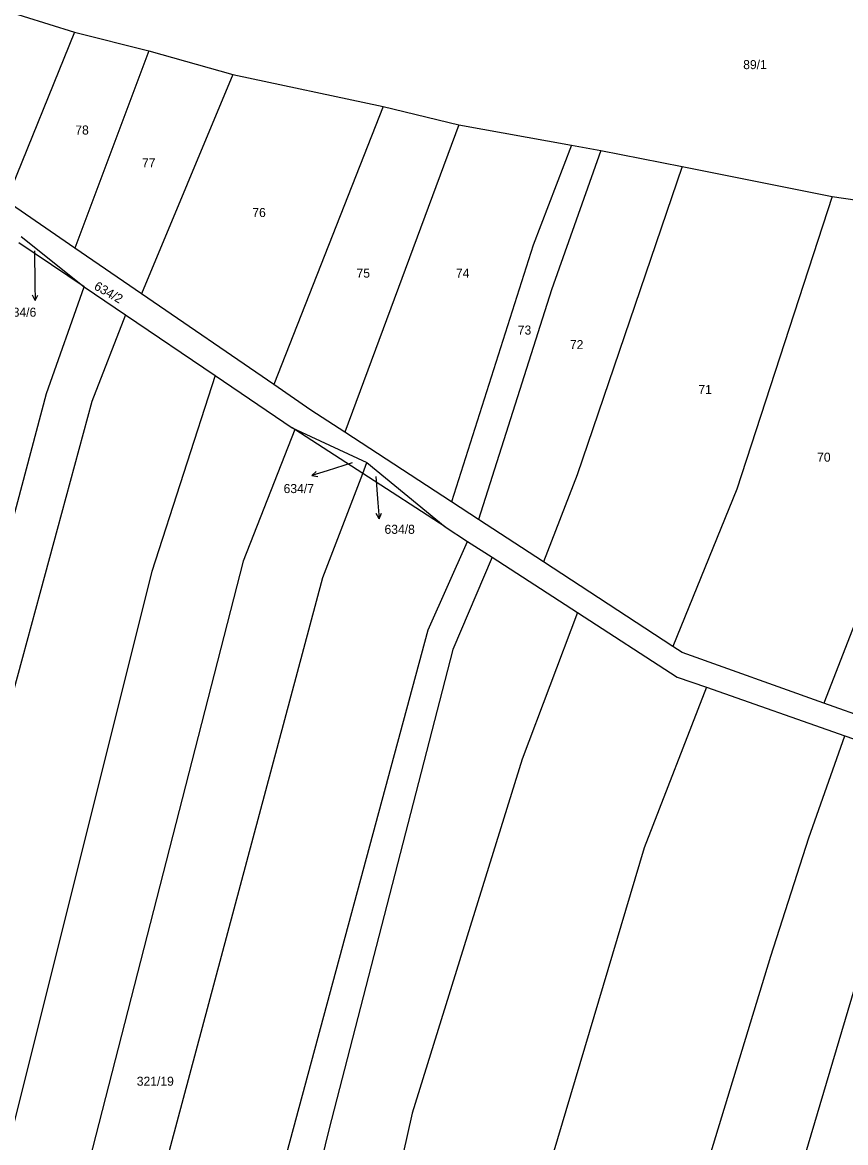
# Model space of a CAD drawing. Extents: x -746176 to -739709, y -1128407 to -1124482.
# Drawn here: x -743602.7 to -743448.2, y -1127556.1 to -1127345.9 of the extents above; entities that cross this region are included whole.
import ezdxf

# ---------------------------------------------------------------- set-up
doc = ezdxf.new("R2010")
doc.units = 0
for name, color, linetype in [('Hranice parcel', 7, 'Continuous'), ('Parcelní čísla', 7, 'Continuous'), ('Pop  PČ popisy', 7, 'Continuous')]:
    doc.layers.add(name, color=color, linetype=linetype)

msp = doc.modelspace()

# ---------------------------------------------------------------- linework, layer by layer
at = {"layer": 'Hranice parcel'}
for p, q in [((-743608.18, -1127342.94), (-743592.88, -1127347.72)), ((-743592.88, -1127347.72), (-743605.72, -1127379.4)), ((-743592.88, -1127347.72), (-743578.94, -1127351.24)), ((-743578.94, -1127351.24), (-743592.83, -1127388.25)), ((-743578.94, -1127351.24), (-743563.19, -1127355.67)), ((-743563.19, -1127355.67), (-743580.36, -1127396.81)), ((-743563.19, -1127355.67), (-743534.99, -1127361.65)), ((-743534.99, -1127361.65), (-743555.5, -1127413.88)), ((-743534.99, -1127361.65), (-743520.78, -1127365.13)), ((-743520.78, -1127365.13), (-743542.21, -1127422.8)), ((-743520.78, -1127365.13), (-743499.65, -1127368.91)), ((-743499.65, -1127368.91), (-743494.17, -1127369.95)), ((-743494.17, -1127369.95), (-743478.91, -1127372.96)), ((-743478.91, -1127372.96), (-743450.74, -1127378.54)), ((-743450.74, -1127378.54), (-743421.13, -1127383.11)), ((-743592.83, -1127388.25), (-743605.72, -1127379.4)), ((-743602.9, -1127386.07), (-743591.07, -1127395.53)), ((-743591.07, -1127395.53), (-743603.32, -1127387.24)), ((-743580.36, -1127396.81), (-743592.83, -1127388.25)), ((-743591.07, -1127395.53), (-743583.33, -1127400.78)), ((-743555.5, -1127413.88), (-743580.36, -1127396.81)), ((-743583.33, -1127400.78), (-743566.53, -1127412.16)), ((-743566.53, -1127412.16), (-743552.04, -1127421.98)), ((-743551.54, -1127422.32), (-743552.04, -1127421.98)), ((-743552.04, -1127421.98), (-743538.08, -1127428.5)), ((-743538.8, -1127430.57), (-743551.54, -1127422.32)), ((-743522.16, -1127435.9), (-743542.21, -1127422.8)), ((-743538.8, -1127430.57), (-743538.08, -1127428.5)), ((-743538.08, -1127428.5), (-743523.36, -1127440.58)), ((-743523.36, -1127440.58), (-743538.8, -1127430.57)), ((-743517.11, -1127439.2), (-743522.16, -1127435.9)), ((-743504.93, -1127447.16), (-743517.11, -1127439.2)), ((-743523.36, -1127440.58), (-743519.14, -1127443.31)), ((-743519.14, -1127443.31), (-743514.57, -1127446.27)), ((-743514.57, -1127446.27), (-743498.56, -1127456.64)), ((-743480.64, -1127463.02), (-743504.93, -1127447.16)), ((-743474.35, -1127470.68), (-743448.36, -1127479.77)), ((-743435.76, -1127479.58), (-743452.29, -1127473.67)), ((-743448.36, -1127479.77), (-743431.85, -1127485.54))]:
    msp.add_line(p, q, dxfattribs=at)
for points in [[(-743499.65, -1127368.91), (-743506.82, -1127387.68), (-743522.16, -1127435.9)], [(-743494.17, -1127369.95), (-743503.41, -1127396.1), (-743517.11, -1127439.2)], [(-743478.91, -1127372.96), (-743498.61, -1127430.83), (-743504.93, -1127447.16)], [(-743450.74, -1127378.54), (-743468.63, -1127433.52), (-743480.64, -1127463.02)], [(-743421.13, -1127383.11), (-743430.01, -1127406.91), (-743443.41, -1127450.8), (-743452.29, -1127473.67)], [(-743681.73, -1127737.55), (-743673.31, -1127708.75), (-743643.68, -1127594.43), (-743625.08, -1127516.64), (-743598.16, -1127415.52), (-743591.07, -1127395.53)], [(-743583.33, -1127400.78), (-743589.64, -1127417.03), (-743612.49, -1127501.11), (-743625.94, -1127556.86), (-743649.9, -1127650.85), (-743673.66, -1127737.68)], [(-743566.53, -1127412.16), (-743578.37, -1127448.95), (-743606.94, -1127562.76), (-743640.25, -1127693.79), (-743653.09, -1127738.43)], [(-743542.21, -1127422.8), (-743548.56, -1127418.65), (-743555.5, -1127413.88)], [(-743551.54, -1127422.32), (-743561.28, -1127447), (-743590.72, -1127561.84), (-743612.33, -1127649.25), (-743636.86, -1127737.44)], [(-743621.23, -1127735.75), (-743612.44, -1127707.12), (-743584.91, -1127601.01), (-743579.58, -1127574.43), (-743546.31, -1127450.09), (-743538.8, -1127430.57)], [(-743599.16, -1127738.75), (-743570.37, -1127633.12), (-743554.73, -1127564.38), (-743526.58, -1127459.91), (-743519.14, -1127443.31)], [(-743514.57, -1127446.27), (-743521.89, -1127463.56), (-743545.21, -1127553.77), (-743561.74, -1127621.6), (-743573.61, -1127667.99), (-743594.04, -1127739.28)], [(-743498.56, -1127456.64), (-743508.94, -1127484.15), (-743529.52, -1127550.64), (-743545.56, -1127622.11), (-743562.33, -1127685.66), (-743579.85, -1127741.23)], [(-743498.56, -1127456.64), (-743479.85, -1127468.76), (-743474.35, -1127470.68)], [(-743452.29, -1127473.67), (-743478.87, -1127464.17), (-743480.64, -1127463.02)], [(-743474.35, -1127470.68), (-743486.04, -1127500.8), (-743505.77, -1127567.21), (-743512.98, -1127598.18)], [(-743487.51, -1127605.98), (-743486.02, -1127599.12), (-743462.28, -1127521.15), (-743455.14, -1127498.91), (-743448.36, -1127479.77)], [(-743431.85, -1127485.54), (-743442.53, -1127513.63), (-743460.53, -1127574.17), (-743468.34, -1127604.77), (-743475.06, -1127627.97)]]:
    msp.add_lwpolyline(points, dxfattribs=at)
at = {"layer": 'Pop  PČ popisy'}
for p, q in [((-743600.38, -1127388.76), (-743600.32, -1127395.1)), ((-743600.32, -1127395.1), (-743600.27, -1127398.1)), ((-743600.27, -1127398.1), (-743600.79, -1127397.11)), ((-743600.27, -1127398.1), (-743599.78, -1127397.09)), ((-743540.79, -1127428.58), (-743545.51, -1127430.04)), ((-743545.51, -1127430.04), (-743548.38, -1127430.92)), ((-743548.38, -1127430.92), (-743547.57, -1127430.15)), ((-743548.38, -1127430.92), (-743547.28, -1127431.1)), ((-743536.35, -1127431.11), (-743535.97, -1127436.06)), ((-743535.97, -1127436.06), (-743535.76, -1127439.05)), ((-743535.76, -1127439.05), (-743536.33, -1127438.09)), ((-743535.76, -1127439.05), (-743535.33, -1127438.02))]:
    msp.add_line(p, q, dxfattribs=at)

# ---------------------------------------------------------------- texts
at = {"layer": 'Parcelní čísla'}
for s, p in [('89/1', (-743467.44, -1127354.66)), ('78', (-743592.75, -1127366.94)), ('77', (-743580.24, -1127373.09)), ('76', (-743559.54, -1127382.42)), ('75', (-743539.99, -1127393.8)), ('74', (-743521.34, -1127393.8)), ('634/6', (-743605.76, -1127401.13)), ('73', (-743509.74, -1127404.49)), ('72', (-743499.96, -1127407.22)), ('71', (-743475.85, -1127415.64)), ('70', (-743453.57, -1127428.34)), ('634/7', (-743553.67, -1127434.23)), ('634/8', (-743534.74, -1127441.88)), ('321/19', (-743581.22, -1127545.47))]:
    msp.add_text(s, height=1.7, dxfattribs=at).set_placement(p)
msp.add_text('634/2', height=1.7, rotation=330, dxfattribs=at).set_placement((-743589.39, -1127395.87))

doc.saveas('drawing.dxf')
